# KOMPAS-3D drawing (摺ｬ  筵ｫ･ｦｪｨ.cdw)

Referenced files in C:\Documents and Settings\GooDMaN\Мои документы\Мои работы для шараги\Работы для помощников\Ремонт рамы тележки\: Рама тележки.cdw
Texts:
  Вставь свой шифр
  Рама тележки
  GooDMaN
  Домашний пк
  Текст на чертеже
  Размерные надписи
  Шероховатость
  Линия-выноска #1
  Линия-выноска #2
  Линия-выноска #3
  Отклонения формы и база
  Заголовок таблицы
  Ячейка таблицы
  Стрелка вида
  Обозначение изменения
  Фигурная скобка
  Номер узла
  Марка координационной оси
  VRCB
  Выносная надпись
  Обозначение узла
  Марка/позиционное обозначение с линией-выноской
  Марка/позиционное обозначение на линии
  Марка/позиционное обозначение без линии-выноски
  Слой 1
  Рама
  тележки
  Иванов
  ПУ-1 гр.№101
  ПЭР.30.4.00.00.22.ВО-
Dimensions and other numbers on the sheet: 7; 1; 2; 3; 4; 5; 6; 8; 9; 0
